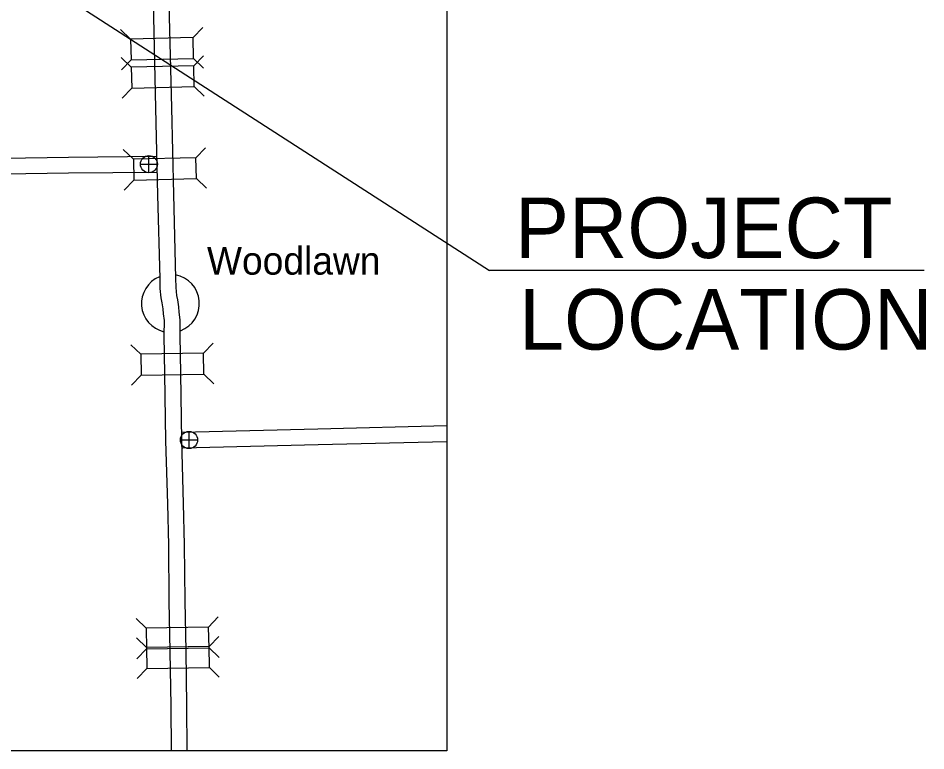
# Model space of a CAD drawing. Extents: x 1367863 to 1368197, y 380048 to 380261.
# Drawn here: x 1367923.7 to 1367953.72, y 380187.5 to 380211.73 of the extents above; entities that cross this region are included whole.
import ezdxf

# ---------------------------------------------------------------- set-up
doc = ezdxf.new("R2010")
doc.units = 0
for name, color, linetype in [('Level 10', 7, 'Continuous'), ('Level 20', 7, 'Continuous'), ('Level 24', 7, 'Continuous'), ('Level 26', 7, 'Continuous'), ('R_Border', 7, 'Continuous'), ('R_No Plot', 7, 'Continuous')]:
    doc.layers.add(name, color=color, linetype=linetype)

msp = doc.modelspace()

# ---------------------------------------------------------------- linework, layer by layer
at = {"layer": 'Level 10'}
for points in [[(1367927.993, 380220.751), (1367928.039, 380218.744), (1367928.086, 380216.374), (1367928.131, 380214.214), (1367928.175, 380211.76), (1367928.243, 380208.75), (1367928.311, 380205.876), (1367928.381, 380203.115), (1367928.388, 380202.786), (1367928.415, 380202.481), (1367928.45, 380202.314), (1367928.479, 380202.115), (1367928.496, 380201.948), (1367928.525, 380201.722), (1367928.521, 380201.231), (1367928.544, 380199.963), (1367928.574, 380197.75), (1367928.635, 380195.666), (1367928.672, 380194.296), (1367928.687, 380192.449), (1367928.718, 380190.782), (1367928.747, 380188.984), (1367928.757, 380187.495)], [(1367928.519, 380220.596), (1367928.562, 380218.755), (1367928.608, 380216.385), (1367928.653, 380214.224), (1367928.697, 380211.77), (1367928.766, 380208.762), (1367928.834, 380205.889), (1367928.903, 380203.127), (1367928.91, 380202.815), (1367928.933, 380202.559), (1367928.965, 380202.406), (1367928.998, 380202.178), (1367929.015, 380202.007), (1367929.048, 380201.753), (1367929.043, 380201.233), (1367929.066, 380199.971), (1367929.096, 380197.761), (1367929.157, 380195.68), (1367929.194, 380194.305), (1367929.21, 380192.456), (1367929.24, 380190.791), (1367929.269, 380188.99), (1367929.279, 380187.495)], [(1367914.545, 380206.947), (1367917.856, 380207.027), (1367918.98, 380207.029), (1367919.879, 380207.016), (1367920.674, 380207.04), (1367923.236, 380207.095), (1367925.359, 380207.131), (1367928.281, 380207.157)], [(1367914.175, 380206.415), (1367917.863, 380206.505), (1367918.977, 380206.507), (1367919.883, 380206.494), (1367920.688, 380206.518), (1367923.246, 380206.573), (1367925.366, 380206.608), (1367928.293, 380206.634)], [(1367937.876, 380198.239), (1367933.606, 380198.134), (1367929.117, 380198.023)], [(1367937.876, 380197.717), (1367933.619, 380197.612), (1367929.147, 380197.502)]]:
    msp.add_lwpolyline(points, dxfattribs=at)
at = {"layer": 'Level 20'}
for p, q in [((1367929.486, 380211.082), (1367929.804, 380211.415)), ((1367927.418, 380211.036), (1367927.086, 380211.353)), ((1367929.507, 380210.152), (1367929.825, 380210.485)), ((1367927.439, 380210.105), (1367927.107, 380210.423)), ((1367927.434, 380210.346), (1367927.116, 380210.014)), ((1367929.502, 380210.393), (1367929.834, 380210.076)), ((1367927.455, 380209.416), (1367927.137, 380209.084)), ((1367929.523, 380209.463), (1367929.855, 380209.145)), ((1367927.51, 380207.062), (1367927.177, 380207.379)), ((1367929.578, 380207.111), (1367929.895, 380207.443)), ((1367927.526, 380206.372), (1367927.209, 380206.04)), ((1367929.594, 380206.421), (1367929.927, 380206.104)), ((1367927.759, 380200.609), (1367927.428, 380200.928)), ((1367929.827, 380200.646), (1367930.146, 380200.977)), ((1367929.839, 380199.957), (1367930.17, 380199.638)), ((1367927.771, 380199.92), (1367927.452, 380199.589)), ((1367927.931, 380191.553), (1367927.6, 380191.873)), ((1367929.999, 380191.591), (1367930.318, 380191.922)), ((1367930.011, 380190.946), (1367930.331, 380191.276)), ((1367927.943, 380190.913), (1367927.612, 380191.232)), ((1367927.943, 380190.864), (1367927.624, 380190.533)), ((1367930.011, 380190.902), (1367930.342, 380190.583)), ((1367927.954, 380190.223), (1367927.634, 380189.893)), ((1367930.022, 380190.257), (1367930.352, 380189.937))]:
    msp.add_line(p, q, dxfattribs=at)
for points in [[(1367927.434, 380210.346), (1367929.502, 380210.393), (1367929.486, 380211.082), (1367927.418, 380211.036)], [(1367929.507, 380210.152), (1367927.439, 380210.105), (1367927.455, 380209.416), (1367929.523, 380209.463)], [(1367929.578, 380207.111), (1367927.51, 380207.062), (1367927.526, 380206.372), (1367929.594, 380206.421)], [(1367927.771, 380199.92), (1367929.839, 380199.957), (1367929.827, 380200.646), (1367927.759, 380200.609)], [(1367927.943, 380190.864), (1367930.011, 380190.902), (1367929.999, 380191.591), (1367927.931, 380191.553)], [(1367927.954, 380190.223), (1367930.022, 380190.257), (1367930.011, 380190.946), (1367927.943, 380190.913)]]:
    msp.add_lwpolyline(points, close=True, dxfattribs=at)
at = {"layer": 'Level 24'}
for start, end in [(112.4902, 256.9056), (290.09, 79.785)]:
    msp.add_arc((1367928.735, 380202.29), 0.958, start, end, dxfattribs=at)
at = {"layer": 'Level 26'}
for p, q in [((1367928.023, 380206.615), (1367928.023, 380207.181)), ((1367927.74, 380206.898), (1367928.306, 380206.898)), ((1367929.35, 380197.494), (1367929.35, 380198.06)), ((1367929.067, 380197.777), (1367929.633, 380197.777))]:
    msp.add_line(p, q, dxfattribs=at)
for centre in [(1367928.023, 380206.898), (1367929.35, 380197.777)]:
    msp.add_circle(centre, 0.283, dxfattribs=at)
at = {"layer": 'R_Border'}
for p in [(1367911.738, 380221.14), (1367953.669, 380203.384)]:
    msp.add_line(p, (1367939.285, 380203.384), dxfattribs=at)
at = {"layer": 'R_No Plot'}
msp.add_lwpolyline([(1367878.711, 380254.093), (1367937.876, 380254.093), (1367937.876, 380187.495), (1367878.711, 380187.495)], close=True, dxfattribs=at)

# ---------------------------------------------------------------- texts
at = {"layer": 'Level 24'}
msp.add_text('Woodlawn', height=0.9194, dxfattribs=at).set_placement((1367929.942, 380203.244))
at = {"layer": 'R_Border'}
for s, p in [('PROJECT', (1367940.131, 380203.792)), ('LOCATION', (1367940.267, 380200.766))]:
    msp.add_text(s, height=2, dxfattribs=at).set_placement(p)

doc.saveas('drawing.dxf')
